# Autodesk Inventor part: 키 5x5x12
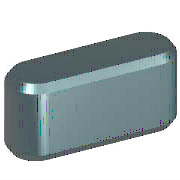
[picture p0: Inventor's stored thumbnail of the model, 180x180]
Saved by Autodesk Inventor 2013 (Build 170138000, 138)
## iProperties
IsCustomPart: 1
Created: 2012-02
Part Number: 키 5x5x12
Material: 강철, 연강
Description: 키 및 해당 키홈
Document SubType Name: Modeling
Standard: KS B 1311
Designer: mduedu
Standards Organization: KS
Language: ko-KR
Size Designation: 5 x 5 x 12
Categories: <MemberInstance><Categories><Category DisplayName="샤프트 부품" InternalName="7f7aeb1f-a693-4053-b835-cee3144e0d98" Mnemonic="SHFT"><Category DisplayName="키" Interna
Density: 1 g/cm^3
Author: mduedu
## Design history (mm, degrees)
workplane "Work Plane1"
workplane "Work Plane2"
sketch "스케치1"
  geometry: L1 (2.5, 2.5)-(9.5, 2.5); L2 (9.5, -2.5)-(2.5, -2.5); L3 (0, 9.4)-(0, -7.4) reference; L4 (-5, 0)-(30, 0) reference; L5 (12, 0)-(12, 7); A1 r 2.5 centre (2.5, 0) between (2.5, 2.5) and (2.5, -2.5); A2 r 2.5 centre (9.5, 0) between (9.5, -2.5) and (9.5, 2.5)
  constraints: 6 end point, 5 point on circle, 4 tangent, 3 point on line, 2 centre point, 1 horizontal, 1 parallel, 1 perpendicular
  dimensions: "d0" = 2.5 radius of A1 (= 0.5 x PB); "d13" = 2.5 radius of A2 (= 0.5 x PB); "d14" = 12 distance between parallel lines of L5 L3 (= NLG)
extrude "본체1" new body sketch "스케치1" taper "d3" = 0 deg; stored distance "d4" = 10
workplane "Work Plane3"
body "Solid1"
chamfer "모따기1" distance "d8" = 0.4 (= PHH); stored, may be unused: second distance "d9" = 0.4 (= PHH), angle "d15" = 45 deg
other parameters: "d1" = -3 (= -PNT), "d2" = 2 (= PH - PNT), "NLG" = 12 [user parameter; used in 3 equation terms], "PB" = 5 [user parameter; used in 2 equation terms], "PNT" = 3 [user parameter; used in 2 equation terms], "PH" = 5 [user parameter; used in 1 equation term], "PHH" = 0.4 [user parameter; used in 2 equation terms], "d10" = 0, "d16" = 0, "d17" = 0, "d18" = 0, "WDMIN" = 12 [user parameter], "PLB2" = 12 (= NLG) [user parameter], "WDMAX" = 17 [user parameter], "PLB1" = 12 (= NLG) [user parameter], "RR" = 0.16 [user parameter], "PUEB" = 2.3 [user parameter]
